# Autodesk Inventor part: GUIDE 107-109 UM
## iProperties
Shininess: 41.0
Angle Display Precision: 2
Document Length Units: 11269
Document Angle Units: 11279
Document Time Units: 11290
Document Mass Units: 11283
Document Length Units Precision: 3
Document Angle Units Precision: 2
Created: 2002-02
Part Number: GUIDE 107-109 UM
Material: Par défaut
Document SubType Name: Modélisation
Designer: Administrateur
Density: 0.0
Volumn: 0.0
Area: 0.0
PropertySet Name: Model Information
Control State: 0
Master: False
Checked Out: False
Author: Administrateur
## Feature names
1. Extrusion1
2. Perçage1 [Hole]
3. Perçage2 [Hole]
